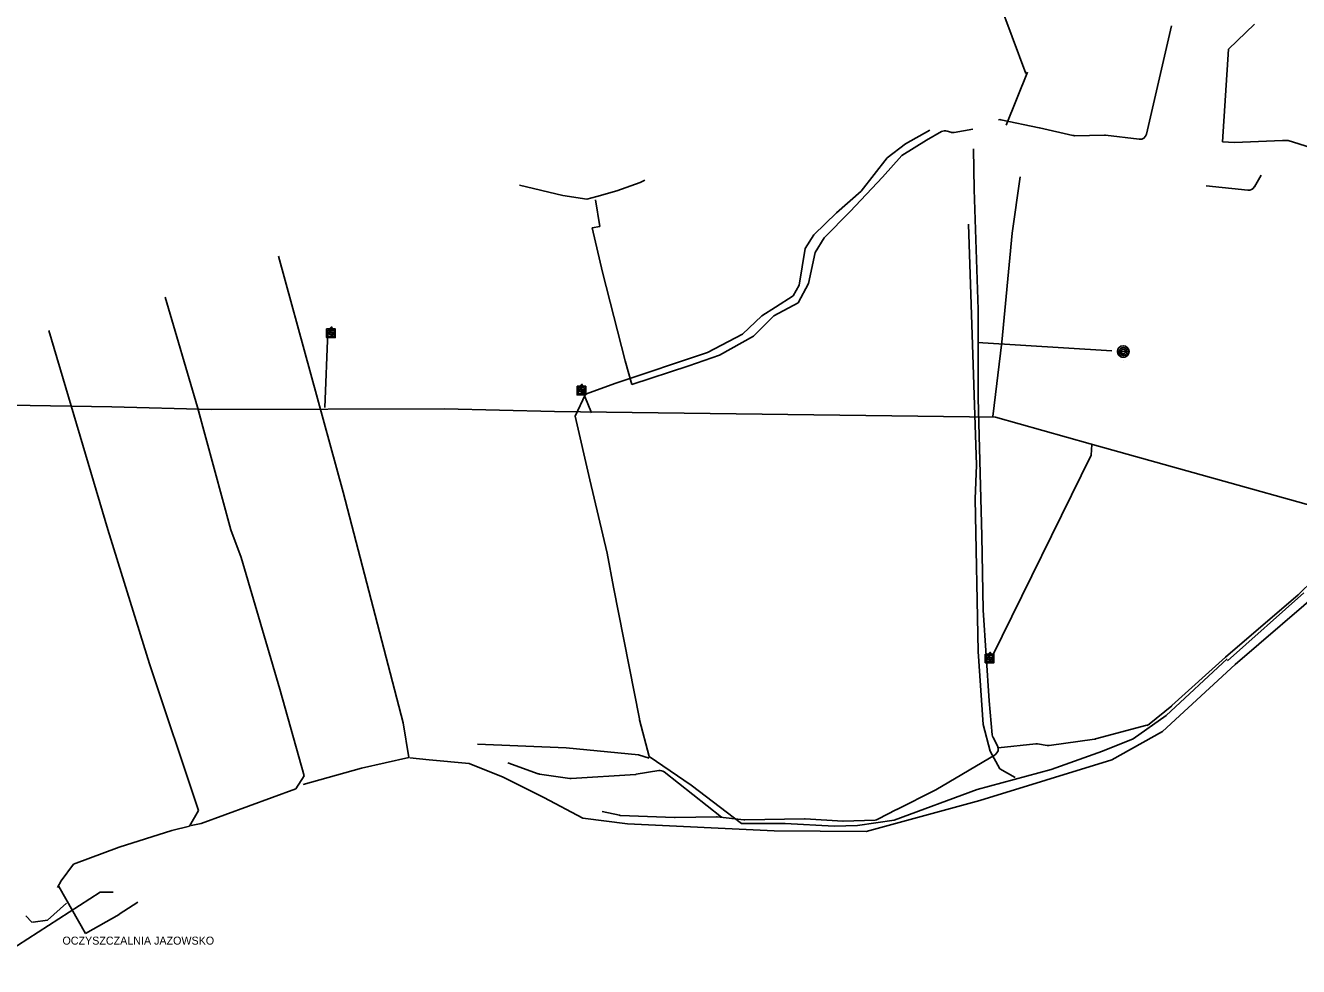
# Model space of a CAD drawing. Extents: x -562329 to -547582, y 191173 to 206137.
# Drawn here: x -550910 to -549002, y 198102 to 199512 of the extents above; entities that cross this region are included whole.
import ezdxf

# ---------------------------------------------------------------- set-up
doc = ezdxf.new("R2010")
doc.units = 0
for name, color, linetype in [('nazwy miejscowości', 7, 'Continuous'), ('nazwy miejscowości DUŻE', 7, 'Continuous'), ('opisy', 7, 'Continuous'), ('ramki A3_A', 7, 'Continuous'), ('strefa - cmentarz', 7, 'Continuous'), ('zmiany', 7, 'Continuous'), ('zmiany_2005', 7, 'Continuous'), ('zmieniane 2006', 7, 'Continuous')]:
    doc.layers.add(name, color=color, linetype=linetype)

msp = doc.modelspace()

# ---------------------------------------------------------------- linework, layer by layer
at = {"layer": 'nazwy miejscowości'}
for p, q in [((-549431.1, 199201.2), (-549418.8, 199285.7)), ((-549446.7, 199037.9), (-549431.1, 199201.2)), ((-550461.5, 198939.9), (-550456.7, 199052.9)), ((-549459.8, 198926.2), (-549446.7, 199037.9))]:
    msp.add_line(p, q, dxfattribs=at)
for points in [[(-552422.2, 199099.8), (-552180.9, 199043.6), (-552087, 199023.6), (-551872.4, 198972.7), (-551762.8, 198947.6), (-551521.9, 198946), (-551449.5, 198945.5), (-551209.2, 198944.9), (-550933.3, 198943.4), (-550780.6, 198940.7)], [(-549456, 198925.3), (-549314, 198885.4), (-548780.9, 198736.4), (-548361.7, 198619.7), (-547964, 198876.4), (-547698.4, 199043.4), (-547581.7, 199112.5), (-547583.5, 199109.8)], [(-550780.6, 198940.7), (-550631.3, 198936.8), (-550281.9, 198937.9), (-550117.1, 198933.7), (-549456, 198925.3)], [(-549311.8, 198884.5), (-549312.8, 198868.4), (-549461.2, 198566.9)]]:
    msp.add_lwpolyline(points, dxfattribs=at)
at = {"layer": 'nazwy miejscowości DUŻE'}
for p, q in [((-549410.6, 199440.5), (-549451.6, 199550.8)), ((-549440.1, 199362.8), (-549408.1, 199442.4)), ((-550061.7, 198932.1), (-550076, 198967.2))]:
    msp.add_line(p, q, dxfattribs=at)
at = {"layer": 'opisy'}
for p, q in [((-549192.4, 199511.5), (-549229.6, 199349.6)), ((-549390.4, 199358.8), (-549447.8, 199370.9)), ((-549559.2, 199340.3), (-549536.7, 199353.3)), ((-549528.4, 199354.1), (-549523.1, 199352.3)), ((-549518.1, 199351.9), (-549490, 199357)), ((-549339.9, 199347.4), (-549390.2, 199358.8)), ((-549292.4, 199347.9), (-549337.5, 199347.1)), ((-549240.5, 199341.9), (-549291.1, 199347.8)), ((-549596.5, 199317.5), (-549559.2, 199340.3)), ((-549489, 199327.6), (-549488, 199266.7)), ((-549625.4, 199285.2), (-549596.5, 199317.5)), ((-549057.9, 199287.9), (-549068, 199270.5)), ((-550104.8, 199257.6), (-550169.5, 199273)), ((-549988.4, 199277.1), (-550023.4, 199264.3)), ((-549981.6, 199280.5), (-549988.4, 199277.1)), ((-549673.9, 199233.3), (-549625.4, 199285.2)), ((-549077.7, 199265.6), (-549140.2, 199272.2)), ((-550068.5, 199252.2), (-550104.8, 199257.6)), ((-550053.7, 199256.2), (-550068.5, 199252.2)), ((-550055.7, 199250.8), (-550049, 199211.1)), ((-550023.4, 199264.3), (-550053.7, 199256.2)), ((-549488, 199266.5), (-549481.8, 199086.9)), ((-549713, 199194.3), (-549673.9, 199233.3)), ((-550049, 199211.1), (-550060.4, 199209.1)), ((-550060.4, 199209.1), (-550044.9, 199142.4)), ((-549726.4, 199172), (-549713, 199194.3)), ((-549736.5, 199125.6), (-549726.4, 199172)), ((-550044.9, 199142.4), (-550011.2, 199009.8)), ((-549752, 199096.6), (-549736.5, 199125.6)), ((-549788.4, 199077.1), (-549752, 199096.6)), ((-549481.8, 199086.6), (-549481.8, 198953.9)), ((-549818.7, 199046.8), (-549788.4, 199077.1)), ((-549869.8, 199018.5), (-549818.7, 199046.8)), ((-549281.7, 199024.7), (-549483, 199037.4)), ((-550011.2, 199009.8), (-550001.1, 198974.1)), ((-550001.1, 198974.1), (-549915.6, 199002.4)), ((-549915.6, 199002.4), (-549869.8, 199018.5)), ((-549481.8, 198953.7), (-549476.3, 198747.4)), ((-549476.3, 198747.3), (-549474.7, 198636.6)), ((-548979.3, 198681.5), (-549001.7, 198659.6)), ((-549002.2, 198659.2), (-549111.1, 198566)), ((-549474.7, 198636.1), (-549465.4, 198500.2)), ((-549111.3, 198565.8), (-549191.5, 198493.2)), ((-549465.4, 198500.2), (-549460.8, 198449.4)), ((-549191.9, 198492.9), (-549225.4, 198465.6)), ((-549229.1, 198463.7), (-549306.3, 198443.2)), ((-549459.6, 198445.6), (-549452.9, 198433)), ((-549395.7, 198435.8), (-549451.9, 198430.1)), ((-549378.5, 198433.5), (-549393.2, 198435.8)), ((-549307.5, 198442.9), (-549375.6, 198433.4)), ((-549456.7, 198419.7), (-549545.6, 198367.1)), ((-550141.5, 198391.1), (-550187.2, 198407.7)), ((-550093.9, 198384), (-550139.5, 198390.6)), ((-549960.6, 198395.8), (-549994.4, 198390.3)), ((-549866.8, 198326.1), (-549952.8, 198393.8)), ((-549995.4, 198390.2), (-550091.9, 198383.9)), ((-549546.2, 198366.7), (-549604, 198337.8)), ((-550019.6, 198328.9), (-550045.8, 198334.6)), ((-549604.2, 198337.7), (-549632.3, 198322.9)), ((-549937, 198325.6), (-550017.9, 198328.7)), ((-549874.3, 198326.6), (-549936.4, 198325.6)), ((-549833, 198321.9), (-549873, 198326.6)), ((-549742.2, 198323.5), (-549831.7, 198321.9)), ((-549685, 198320.3), (-549741.4, 198323.4)), ((-549636.6, 198321.8), (-549684.2, 198320.3))]:
    msp.add_line(p, q, dxfattribs=at)
for centre, start, end in [((-549449.9, 199361.2), 78.1113, 100.008), ((-549531.7, 199344.6), 70.9065, 120.0686), ((-549519.8, 199361.7), 250.9065, 280.3048), ((-549392.4, 199349.1), 77.1957, 78.1113), ((-549337.6, 199357.1), 257.1957, 270.9548), ((-549292.3, 199337.9), 83.3333, 90.9548), ((-549239.3, 199351.8), 263.3333, 347.0822), ((-549076.7, 199275.5), 263.9275, 329.7746), ((-549478, 199266.8), 180.9167, 181.9921), ((-549491.8, 199086.6), 360, 1.9921), ((-549471.8, 198953.9), 180, 181.5189), ((-549486.3, 198747.2), 0.8069, 1.5189), ((-549008.7, 198666.8), 310.5543, 314.3097), ((-549464.7, 198636.8), 180.8069, 183.9005), ((-549104.6, 198558.4), 130.5543, 132.1579), ((-549198.2, 198500.6), 309.1933, 312.1579), ((-549450.8, 198450.3), 185.2418, 208.1416), ((-549231.7, 198473.3), 284.8586, 309.1933), ((-549461.8, 198428.3), 300.6421, 28.1416), ((-549394.7, 198425.9), 81.1193, 95.8696), ((-549377, 198443.3), 261.1193, 277.9435), ((-549308.9, 198452.8), 277.9435, 284.8586), ((-550138.1, 198400.5), 250.0169, 261.7808), ((-549959, 198386), 51.7979, 99.335), ((-550092.5, 198393.9), 261.7808, 273.7113), ((-549996.1, 198400.1), 273.7113, 279.335), ((-549550.7, 198375.7), 296.5651, 300.6421), ((-549599.5, 198328.9), 116.5651, 117.7585), ((-550017.5, 198338.7), 257.8285, 267.7832), ((-549936.6, 198335.6), 267.7832, 270.9629), ((-549874.2, 198316.6), 83.4181, 90.9629), ((-549831.9, 198331.9), 263.4181, 271.0051), ((-549742, 198313.5), 86.8202, 91.0051), ((-549684.5, 198330.3), 266.8202, 271.8087), ((-549636.9, 198331.8), 271.8087, 297.7585)]:
    msp.add_arc(centre, 10, start, end, dxfattribs=at)
at = {"layer": 'ramki A3_A'}
for p, q in [((-550456.8, 199046.4), (-550456.8, 199055.9)), ((-550456.8, 199055.9), (-550453.3, 199055.9)), ((-550452.3, 199046.4), (-550456.8, 199046.4)), ((-550452.8, 199057.7), (-550455.3, 199049.4)), ((-550455.3, 199049.4), (-550451, 199050.8)), ((-550454.3, 199057.7), (-550452.8, 199057.7)), ((-550453.2, 199051.6), (-550451.3, 199057.7)), ((-550448.8, 199053), (-550453.2, 199051.6)), ((-550451, 199050.8), (-550452.8, 199044.7)), ((-550452.8, 199044.7), (-550451.3, 199044.7)), ((-550452.8, 199044.7), (-550451.3, 199044.7)), ((-550451.9, 199055.9), (-550447.3, 199055.9)), ((-550451.3, 199057.7), (-550449.8, 199057.7)), ((-550451.3, 199044.7), (-550448.8, 199053)), ((-550447.3, 199046.4), (-550450.8, 199046.4)), ((-550447.3, 199055.9), (-550447.3, 199046.4)), ((-550081.5, 198960.5), (-550081.5, 198970)), ((-550081.5, 198970), (-550078, 198970)), ((-550077.5, 198971.8), (-550080, 198963.4)), ((-550080, 198963.4), (-550075.6, 198964.9)), ((-550079, 198971.8), (-550077.5, 198971.8)), ((-550077.8, 198965.7), (-550076, 198971.8)), ((-550073.5, 198967.1), (-550077.8, 198965.7)), ((-550075.6, 198964.9), (-550077.5, 198958.8)), ((-550076.5, 198970), (-550072, 198970)), ((-550076, 198971.8), (-550074.5, 198971.8)), ((-550076, 198958.8), (-550073.5, 198967.1)), ((-550072, 198970), (-550072, 198960.5)), ((-550077, 198960.5), (-550081.5, 198960.5)), ((-550077.5, 198958.8), (-550076, 198958.8)), ((-550077.5, 198958.8), (-550076, 198958.8)), ((-550072, 198960.5), (-550075.5, 198960.5)), ((-549469.6, 198559.1), (-549469.6, 198568.6)), ((-549469.6, 198568.6), (-549466.1, 198568.6)), ((-549465.6, 198570.3), (-549468.1, 198562)), ((-549468.1, 198562), (-549463.7, 198563.4)), ((-549467.1, 198570.3), (-549465.6, 198570.3)), ((-549465.9, 198564.2), (-549464.1, 198570.3)), ((-549461.6, 198565.7), (-549465.9, 198564.2)), ((-549463.7, 198563.4), (-549465.6, 198557.4)), ((-549464.6, 198568.6), (-549460.1, 198568.6)), ((-549464.1, 198570.3), (-549462.6, 198570.3)), ((-549464.1, 198557.4), (-549461.6, 198565.7)), ((-549460.1, 198568.6), (-549460.1, 198559.1)), ((-549465, 198559.1), (-549469.6, 198559.1)), ((-549465.6, 198557.4), (-549464.1, 198557.4)), ((-549465.6, 198557.4), (-549464.1, 198557.4)), ((-549460.1, 198559.1), (-549463.5, 198559.1))]:
    msp.add_line(p, q, dxfattribs=at)
for points in [[(-550449.8, 199057.7), (-550451.2, 199060.5), (-550454.3, 199057.7)], [(-550074.5, 198971.8), (-550075.9, 198974.6), (-550079, 198971.8)], [(-549462.6, 198570.3), (-549464, 198573.2), (-549467.1, 198570.3)]]:
    msp.add_lwpolyline(points, dxfattribs=at)
for points in [[(-550458.6, 199057.7), (-550445.6, 199057.7), (-550445.6, 199044.7), (-550458.6, 199044.7)], [(-550083.2, 198971.8), (-550070.2, 198971.8), (-550070.2, 198958.8), (-550083.2, 198958.8)], [(-549471.3, 198570.3), (-549458.3, 198570.3), (-549458.3, 198557.4), (-549471.3, 198557.4)]]:
    msp.add_lwpolyline(points, close=True, dxfattribs=at)
at = {"layer": 'strefa - cmentarz'}
for p, q in [((-549270.5, 199023.7), (-549273.1, 199023.7)), ((-549261, 199023.7), (-549267.9, 199023.7)), ((-549255.8, 199023.7), (-549258.4, 199023.7)), ((-549264.5, 199010.1), (-549264.5, 199010.1))]:
    msp.add_line(p, q, dxfattribs=at)
for radius in [8.66, 6.06, 3.46]:
    msp.add_circle((-549264.5, 199023.7), radius, dxfattribs=at)
for radius, start, end in [(8.66, 180, 240), (6.06, 180, 0), (8.66, 240, 0), (3.46, 180, 240), (3.46, 240, 0)]:
    msp.add_arc((-549264.5, 199023.7), radius, start, end, dxfattribs=at)
at = {"layer": 'zmiany'}
for p, q in [((-549067.6, 199514.2), (-549106.9, 199477)), ((-549106.9, 199477), (-549115.8, 199337.8)), ((-549554.2, 199355.6), (-549590.9, 199334.7)), ((-549554.2, 199355.6), (-549590.9, 199334.7)), ((-549590.9, 199334.7), (-549618.3, 199313.8)), ((-549590.9, 199334.7), (-549618.3, 199313.8)), ((-549115.8, 199337.8), (-549097.9, 199337.1)), ((-549097.9, 199337.1), (-549025.6, 199339.9)), ((-549025.6, 199339.9), (-549017.3, 199339.9)), ((-549017.3, 199339.9), (-548953.3, 199319.9)), ((-549618.3, 199313.8), (-549657.5, 199264.1)), ((-549618.3, 199313.8), (-549657.5, 199264.1)), ((-549657.5, 199264.1), (-549694.1, 199231.5)), ((-549657.5, 199264.1), (-549694.1, 199231.5)), ((-549694.1, 199231.5), (-549728.1, 199198.8)), ((-549694.1, 199231.5), (-549728.1, 199198.8)), ((-549496.3, 199214.8), (-549484.3, 198853.7)), ((-549728.1, 199198.8), (-549741.2, 199177.9)), ((-549728.1, 199198.8), (-549741.2, 199177.9)), ((-549741.2, 199177.9), (-549750.3, 199123)), ((-549741.2, 199177.9), (-549750.3, 199123)), ((-550530.7, 199166.4), (-550433.8, 198812.9)), ((-549750.3, 199123), (-549759.5, 199107.3)), ((-549750.3, 199123), (-549759.5, 199107.3)), ((-550700.6, 199105.4), (-550652.2, 198940.2)), ((-549759.5, 199107.3), (-549785.6, 199090.3)), ((-549759.5, 199107.3), (-549785.6, 199090.3)), ((-549785.6, 199090.3), (-549806.5, 199077.2)), ((-549785.6, 199090.3), (-549806.5, 199077.2)), ((-549806.5, 199077.2), (-549835.3, 199049.7)), ((-549806.5, 199077.2), (-549835.3, 199049.7)), ((-549835.3, 199049.7), (-549887.6, 199022.3)), ((-549835.3, 199049.7), (-549887.6, 199022.3)), ((-549887.6, 199022.3), (-550024.9, 198976.5)), ((-549887.6, 199022.3), (-550024.9, 198976.5)), ((-550024.9, 198976.5), (-550070.6, 198959.6)), ((-550024.9, 198976.5), (-550070.6, 198959.6)), ((-550070.6, 198959.6), (-550086.3, 198926.9)), ((-550070.6, 198959.6), (-550086.3, 198926.9)), ((-550652.2, 198940.2), (-550602.3, 198756.6)), ((-550086.3, 198926.9), (-550064.1, 198831.4)), ((-550086.3, 198926.9), (-550064.1, 198831.4)), ((-549484.3, 198853.7), (-549486.7, 198803.1)), ((-550064.1, 198831.4), (-550037.9, 198721.6)), ((-550064.1, 198831.4), (-550037.9, 198721.6)), ((-550433.8, 198812.9), (-550343.7, 198467.6)), ((-549486.7, 198803.1), (-549481.9, 198574.4)), ((-550602.3, 198756.6), (-550586.6, 198715)), ((-550586.6, 198715), (-550528.6, 198517.7)), ((-550037.9, 198721.6), (-550028.8, 198670.7)), ((-550037.9, 198721.6), (-550028.8, 198670.7)), ((-550028.8, 198670.7), (-549989.6, 198473.3)), ((-550028.8, 198670.7), (-549989.6, 198473.3)), ((-549108.3, 198560.1), (-548993.9, 198662.1)), ((-549481.9, 198574.4), (-549474.7, 198464.8)), ((-549200, 198478.5), (-549108.5, 198563.5)), ((-549200, 198478.5), (-549108.5, 198563.5)), ((-550528.6, 198517.7), (-550492.5, 198388.1)), ((-550343.7, 198467.6), (-550335.5, 198415.7)), ((-549989.6, 198473.3), (-549989.6, 198472)), ((-549989.6, 198473.3), (-549989.6, 198472)), ((-549989.6, 198472), (-549975.2, 198417)), ((-549989.6, 198472), (-549975.2, 198417)), ((-549249.7, 198443.2), (-549200, 198478.5)), ((-549249.7, 198443.2), (-549200, 198478.5)), ((-549474.7, 198464.8), (-549463.8, 198425.1)), ((-550232.7, 198435.4), (-550099.4, 198430.1)), ((-550099.4, 198430.1), (-549990.9, 198419.7)), ((-549295.4, 198424.9), (-549249.7, 198443.2)), ((-549295.4, 198424.9), (-549249.7, 198443.2)), ((-550335.5, 198415.7), (-550406.5, 198399.3)), ((-549990.9, 198419.7), (-549975.2, 198414.4)), ((-549975.2, 198417), (-549912.4, 198373.9)), ((-549975.2, 198417), (-549912.4, 198373.9)), ((-549463.8, 198425.1), (-549449.4, 198398.6)), ((-549372.5, 198397.4), (-549295.4, 198424.9)), ((-549372.5, 198397.4), (-549295.4, 198424.9)), ((-550406.5, 198399.3), (-550493.8, 198374.8)), ((-549483.7, 198367.4), (-549372.5, 198397.4)), ((-549483.7, 198367.4), (-549372.5, 198397.4)), ((-549449.4, 198398.6), (-549426.5, 198385.4)), ((-550492.5, 198388.1), (-550504.7, 198368.3)), ((-549912.4, 198373.9), (-549836.6, 198316.4)), ((-549912.4, 198373.9), (-549836.6, 198316.4)), ((-550504.7, 198368.3), (-550646.7, 198316.4)), ((-549607.8, 198321.6), (-549483.7, 198367.4)), ((-549607.8, 198321.6), (-549483.7, 198367.4)), ((-550646.7, 198316.4), (-550661.7, 198313.7)), ((-549836.6, 198316.4), (-549771.2, 198316.4)), ((-549836.6, 198316.4), (-549771.2, 198316.4)), ((-549771.2, 198316.4), (-549698, 198312.5)), ((-549771.2, 198316.4), (-549698, 198312.5)), ((-549662.7, 198313.8), (-549607.8, 198321.6)), ((-549662.7, 198313.8), (-549607.8, 198321.6)), ((-549698, 198312.5), (-549662.7, 198313.8)), ((-549698, 198312.5), (-549662.7, 198313.8)), ((-550971.2, 198102.3), (-550798.3, 198213.8)), ((-550798.3, 198213.8), (-550778.5, 198213.8))]:
    msp.add_line(p, q, dxfattribs=at)
at = {"layer": 'zmiany_2005'}
for p, q in [((-548885.1, 198737.1), (-549096.7, 198554.7)), ((-549096.7, 198554.7), (-549205.9, 198454.3)), ((-549205.9, 198454.3), (-549281.6, 198412.1)), ((-550304.7, 198412.1), (-550333.8, 198415)), ((-550245, 198406.3), (-550304.7, 198412.1)), ((-549281.6, 198412.1), (-549479.5, 198351)), ((-550194.1, 198385.9), (-550245, 198406.3)), ((-550132.9, 198355.3), (-550194.1, 198385.9)), ((-550074.7, 198324.8), (-550132.9, 198355.3)), ((-549479.5, 198351), (-549649.8, 198304.4)), ((-550007.8, 198316), (-550074.7, 198324.8)), ((-549788, 198305.8), (-550007.8, 198316)), ((-549649.8, 198304.4), (-549788, 198305.8))]:
    msp.add_line(p, q, dxfattribs=at)
at = {"layer": 'zmieniane 2006'}
for p, q in [((-550875.2, 199055.4), (-550786.4, 198757)), ((-550786.4, 198757), (-550724.3, 198555.9)), ((-550724.3, 198555.9), (-550650.6, 198336.2)), ((-550650.6, 198336.2), (-550664, 198312.8)), ((-550690.8, 198306.1), (-550769.6, 198280.9)), ((-550664, 198312.8), (-550690.8, 198306.1)), ((-550769.6, 198280.9), (-550838.3, 198255.8)), ((-550838.3, 198255.8), (-550856.8, 198230.6)), ((-550856.8, 198230.6), (-550862, 198220.8)), ((-550860.1, 198222.3), (-550819.9, 198151.8)), ((-550876.9, 198172), (-550848.4, 198197.1)), ((-550769.6, 198180.5), (-550741.5, 198198.8)), ((-550909.7, 198178.3), (-550900.3, 198168.6)), ((-550900.3, 198168.6), (-550899.3, 198168.6)), ((-550898.7, 198168.6), (-550876.9, 198172)), ((-550819.9, 198151.8), (-550769.6, 198180.3))]:
    msp.add_line(p, q, dxfattribs=at)

# ---------------------------------------------------------------- texts
at = {"layer": 'zmiany_2005'}
msp.add_text('OCZYSZCZALNIA JAZOWSKO', height=12, dxfattribs=at).set_placement((-550854.6, 198135.1))

doc.saveas('drawing.dxf')
